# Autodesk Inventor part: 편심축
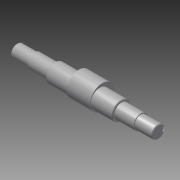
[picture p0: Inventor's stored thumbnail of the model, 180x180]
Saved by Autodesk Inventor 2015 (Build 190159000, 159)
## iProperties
Created: 2015-10
Part Number: 편심축
Document SubType Name: Modeling
Designer: mdu
Density: 7.86 g/cm^3
Material: Steel, Mild
Mass: 1327.93 g
Surface Area: 248.524 cm^2
Volume: 168.947 cm^3
Appearance: Steel
Author: mdu
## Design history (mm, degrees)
sketch "스케치1"
  geometry: L1 (-20.5, -41.331)-(-20.5, 32.669) reference; L2 (7.5, -30.031)-(7.5, 21.369) reference; L3 (135.5, -30.331)-(135.5, 21.669) reference; L4 (121.5, 21.369)-(121.5, -30.031) reference; L5 (184.5, -4.331)-(-57.5, -4.331); L6 (184.5, -4.331)-(184.5, 6.669); L7 (154.5, 8.169)-(121.5, 8.169); L8 (121.5, 8.169)-(121.5, 11.669); L9 (121.5, 11.669)-(7.5, 11.669); L10 (7.5, 11.669)-(7.5, 8.169); L11 (7.5, 8.169)-(-27.5, 8.169); L12 (-27.5, 8.169)-(-27.5, 6.669); L13 (-27.5, 6.669)-(-57.5, 6.669); L14 (-57.5, 6.669)-(-57.5, -4.331); L15 (154.5, 8.169)-(154.5, 6.669); L16 (154.5, 6.669)-(184.5, 6.669); C1 r 32.5 at (64.5, -4.331) reference; 1 further point
  constraints: 24 end point, 8 perpendicular, 5 point on line, 3 parallel, 2 collinear
  dimensions: "d1" = 25 diameter of L11 L5; "d2" = 32 diameter of L9 L5; "d3" = 22 diameter of L13 L5; "d4" = 35 distance of L10.end L11.end; "d5" = 30 distance of L12.end L13.end; "d15" = 33 distance of L7.start L7.end; "d26" = 30 distance of L15.end L6.end
revolve "회전1" sketch "스케치1" stored, may be unused: angle "d6" = 90 deg
node "작업 평면1"
sketch "스케치2"
  geometry: C1 r 16 at (0, 0) reference; C2 r 16 at (0, 0) reference; C3 r 20.75 at (0, 4); C4 r 16 at (0, 0) reference; 1 further point
  constraints: 1 centre point, 1 vertical alignment
  dimensions: "d8" = 41.5 diameter of C3; "d25" = 4 distance of C3.centre C1.centre
extrude "돌출1" join sketch "스케치2" stored distance "d9" = 40; taper "d10" = 0 deg
chamfer "모따기1" distance "d11" = 1; stored, may be unused: second distance "d12" = 2, angle "d13" = 45 deg
node "작업 평면2"
sketch "스케치3"
  geometry: L1 (-15, -10)-(-15, 10) reference; L2 (-15, 3)-(0, 3); L3 (0, -3)-(-15, -3); A1 r 3 centre (0, 0) between (0, -3) and (0, 3); 2 further points
  constraints: 4 end point, 2 perpendicular, 2 point on circle, 2 point on line, 2 tangent, 1 centre point, 1 horizontal alignment, 1 midpoint
  dimensions: "d16" = 18 dimension on A1 L1; "d17" = 6 distance between parallel lines of L3 L2
extrude "돌출2" cut sketch "스케치3" distance "d18" = 3.5; taper "d19" = 0 deg
node "작업 평면3"
node "솔리드1"
mirror "대칭1"
node "참조1"
node "참조2"
node "참조3"
node "참조4"
node "참조5"
node "투영된 루프1"
